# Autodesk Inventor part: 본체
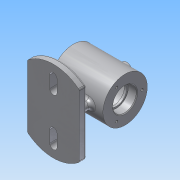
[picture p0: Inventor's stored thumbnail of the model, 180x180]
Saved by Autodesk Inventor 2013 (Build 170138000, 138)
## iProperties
Created: 2017-12
Part Number: 본체
Material: 알루미늄 6061
Document SubType Name: Modeling
Designer: Administrator
Density: 2.71 g/cm^3
Mass: 467.691 g
Surface Area: 486.469 cm^2
Volume: 172.58 cm^3
Author: Administrator
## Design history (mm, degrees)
sketch "스케치1"
  geometry: L1 (-35, 0)-(35, 0); L2 (-35, 0)-(-35, 16); L3 (-35, 30)-(35, 30); L4 (35, 30)-(35, 16); L5 (-35, 16)-(-23, 16); L6 (-23, 16)-(-23, 14); L7 (-23, 14)-(-20, 14); L8 (-20, 14)-(-20, 25); L9 (-20, 25)-(20, 25); L10 (20, 25)-(20, 14); L11 (20, 14)-(23, 14); L12 (23, 14)-(23, 16); L13 (23, 16)-(35, 16); L14 (-35, 16)-(-35, 30); L15 (35, 16)-(35, 0); 3 further points
  constraints: 30 end point, 10 parallel, 9 perpendicular, 2 coincident, 2 midpoint, 1 horizontal, 1 vertical alignment
  dimensions: "d0" = 70 distance of L1.start L1.end; "d2" = 60 diameter of L3 L1; "d3" = 32 diameter of L13 L1; "d4" = 28 diameter of L11 L1; "d5" = 12 distance of L12.end L4.end; "d6" = 50 diameter of L9 L1; "d7" = 32 diameter of L5 L1; "d8" = 28 diameter of L7 L1; "d9" = 12 distance of L2.end L5.end; "d10" = 40 distance of L8.end L9.end
revolve "회전1" sketch "스케치1" stored, may be unused: angle "d11" = 90 deg
node "작업 평면1"
sketch "스케치2"
  geometry: L1 (-35, 42.426)-(-35, -42.426); L2 (35, 42.426)-(35, -42.426); L3 (-5, 40)-(-5, 24); L4 (5, 24)-(5, 40); L5 (-5, -40)-(-5, -24); L6 (5, -24)-(5, -40); L7 (-15, 5)-(15, 5); L8 (15, -5)-(-15, -5); A1 r 55 centre (0, 0) between (35, 42.426) and (-35, 42.426); A2 r 55 centre (0, 0) between (35, -42.426) and (35, 42.426); A3 r 55 centre (0, 0) between (-35, 42.426) and (-35, -42.426); A4 r 55 centre (0, 0) between (-35, -42.426) and (35, -42.426); A5 r 5 centre (0, 24) between (-5, 24) and (5, 24); A6 r 5 centre (0, 40) between (5, 40) and (-5, 40); A7 r 5 centre (0, -24) between (5, -24) and (-5, -24); A8 r 5 centre (0, -40) between (-5, -40) and (5, -40); A9 r 5 centre (15, 0) between (15, -5) and (15, 5); A10 r 5 centre (-15, 0) between (-15, 5) and (-15, -5); 1 further point
  constraints: 21 point on circle, 16 end point, 12 tangent, 10 centre point, 6 parallel, 2 vertical alignment, 1 coincident, 1 horizontal alignment, 1 perpendicular, 1 vertical
  dimensions: "d13" = 110 diameter of A1; "d14" = 70 distance between parallel lines of L1 L2; "d15" = 35 distance from line of point (0, 0) L2 (= 0.5 x d14); "d16" = 5 radius of A6; "d17" = 16 distance of A5.centre A6.centre; "d18" = 24 distance of point (0, 0) A5.centre; "d19" = 5 radius of A7; "d20" = 24 distance of point (0, 0) A7.centre; "d21" = 16 distance of A8.centre A7.centre; "d22" = 5 radius of A10; "d23" = 30 distance of A9.centre A10.centre; "d24" = 15 distance of A9.centre point (0, 0) (= 0.5 x d23)
extrude "돌출1" join sketch "스케치2" distance "d25" = 10; taper "d26" = 0 deg
extrude "돌출2" join sketch "스케치2" stored distance "d27" = 10; taper "d28" = 0 deg
sketch "스케치3"
  geometry: L1 (0, 0)-(0, 23); C1 r 16 at (0, 0) reference
  constraints: 2 end point, 1 vertical
  dimensions: "d29" = 23 distance of L1.start L1.end
hole "구멍1" sketch "스케치3" at (0, 23) diameter "d30" = 3.242; stored, may be unused: countersink angle "d34" = 90 deg, drill point angle "d36" = 118 deg; dims "d31" = 8, "d32" = 4, "d33" = 2, "d35" = 10
node "작업 평면2"
sketch "스케치4"
  geometry: C1 r 8 at (0, 0); 1 further point
  constraints: 1 centre point, 1 coincident
  dimensions: "d41" = 16 diameter of C1
extrude "돌출3" join sketch "스케치4" stored distance "d42" = 10; taper "d43" = 0 deg
sketch "스케치5"
  geometry: C1 r 8 at (0, 0) reference; C2 r 4 at (0, 0)
  constraints: 1 centre point, 1 coincident
  dimensions: "d44" = 8 diameter of C2
extrude "돌출4" cut sketch "스케치5" stored distance "d46" = 10; taper "d47" = 0 deg
fillet "모깎기2" dims "d49" = 3
fillet "모깎기4" dims "d51" = 5, "d53" = 3
chamfer "모따기1" distance "d54" = 1; stored, may be unused: second distance "d55" = 2, angle "d56" = 45 deg
fillet "모깎기6" dims "d57" = 3, "d58" = 0.3
node "작업 평면3"
sketch "스케치6"
  geometry: L1 (-35, 30)-(-35, -30) reference; L2 (35, 30)-(-35, 30) reference; 2 further points
  constraints: 1 other
  dimensions: "d60" = 35 distance from line of L1 point (0, 0); "d61" = 30 distance from line of L2 point (0, 0)
feature "엠보싱1" sketch "스케치6" dims "d0" = 70, "d2" = 60, "d3" = 32, "d4" = 28, "d5" = 12, "d6" = 50, "d7" = 32, "d8" = 28, "d9" = 12, "d10" = 40, "d62" = 0.5, "d63" = 0
node "솔리드1"
pattern_circular "원형 패턴1" dims angle "d38" = 360 deg
mirror "대칭1"
other parameters: "d12" = -62, "d40" = 37, "d59" = -46
